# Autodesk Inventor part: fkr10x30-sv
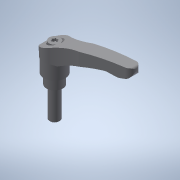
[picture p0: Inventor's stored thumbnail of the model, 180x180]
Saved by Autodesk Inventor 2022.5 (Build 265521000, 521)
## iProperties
Created: 2017-09
Part Number: fkr10x30-sv
Material: 一般
Document SubType Name: Modeling
Designer: imaocorp
Density: 1 g/cm^3
Appearance: 既定
Author: imaocorp
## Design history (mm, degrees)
node "fkr10x30-sv.x_t1"
node "fkr10x30-sv"
node "Base1"
